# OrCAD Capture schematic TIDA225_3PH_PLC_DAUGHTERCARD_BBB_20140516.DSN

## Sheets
1 P05 - Zero Crossing Detector: size B; title: Zero Crossing Detector; rev: 1.2; company: Smart Grid Solutions; note: TIDA-00225_3PH_PLC_DAUGHTERCARD_BBB; note: Texas Instruments, Inc.; note: 12500 TI Blvd
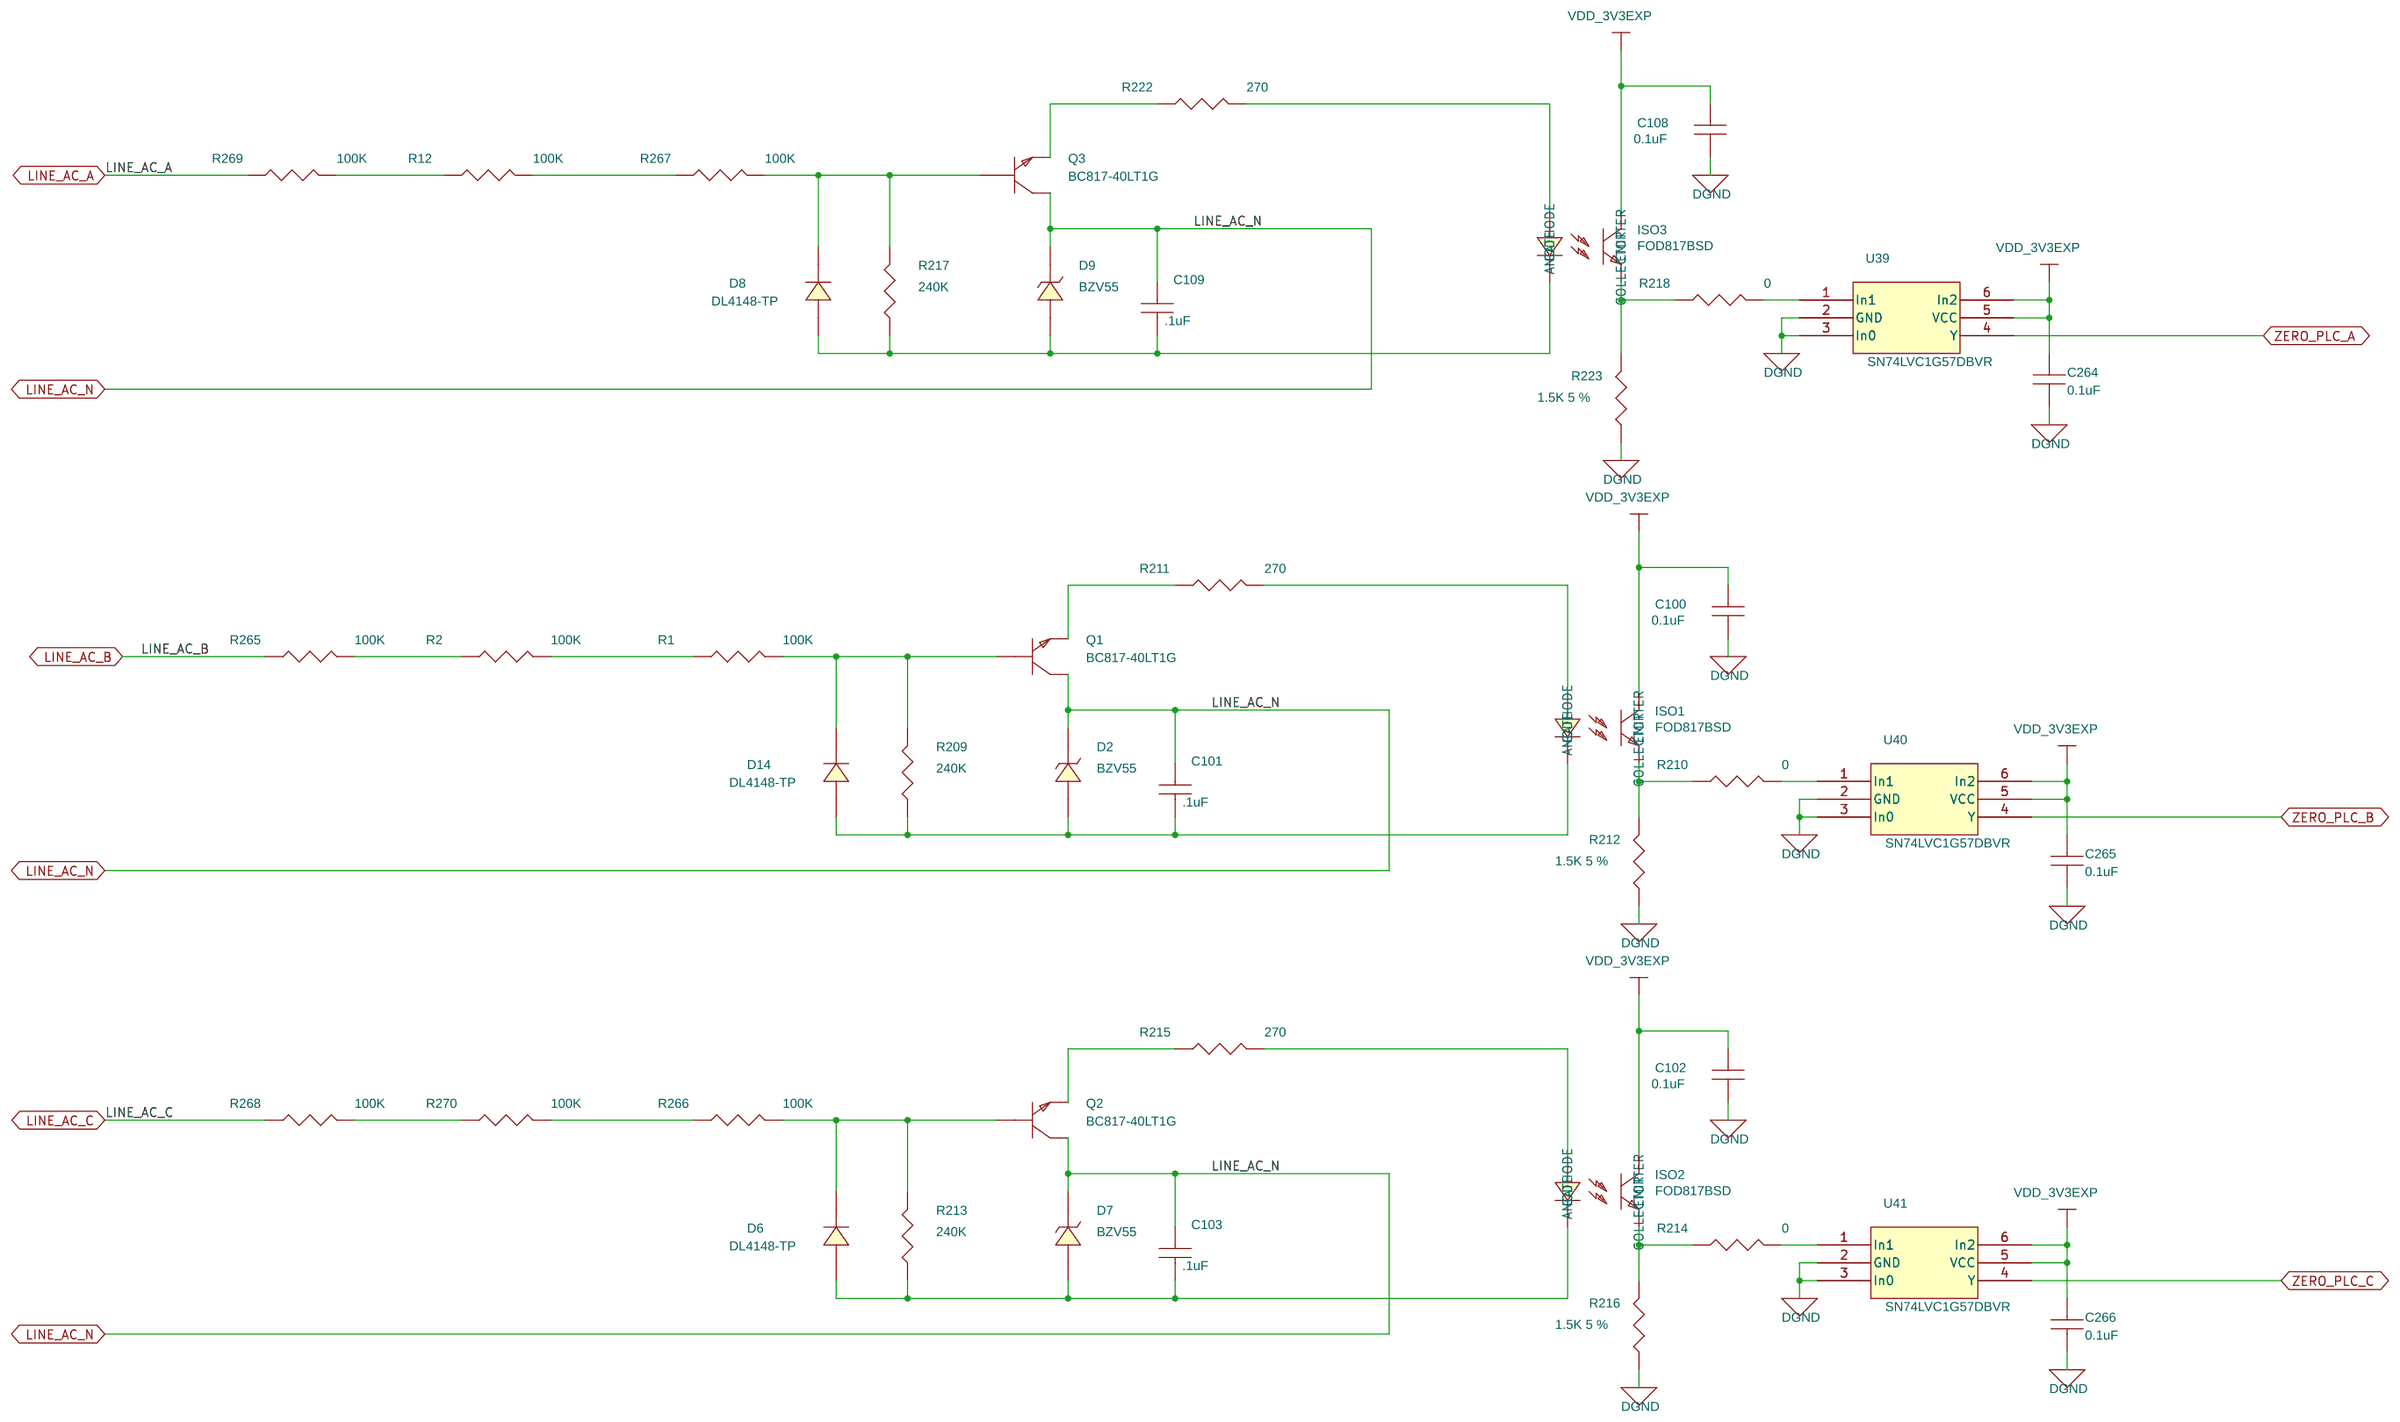
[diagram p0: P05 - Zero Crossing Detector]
2 P01 - Title Page: title: Title Page
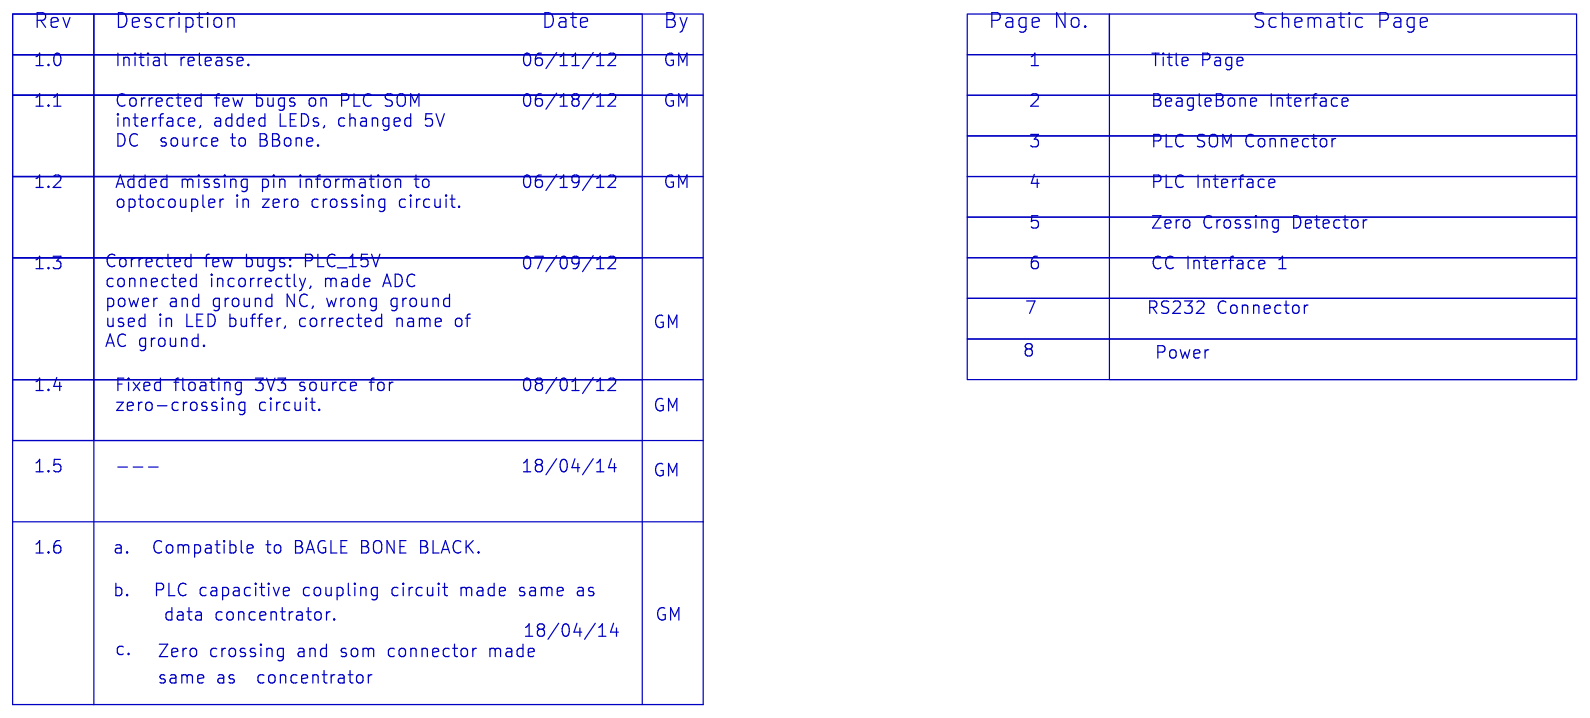
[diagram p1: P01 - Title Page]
3 P06 - CC Interface 1: size B; title: CC Interface 1
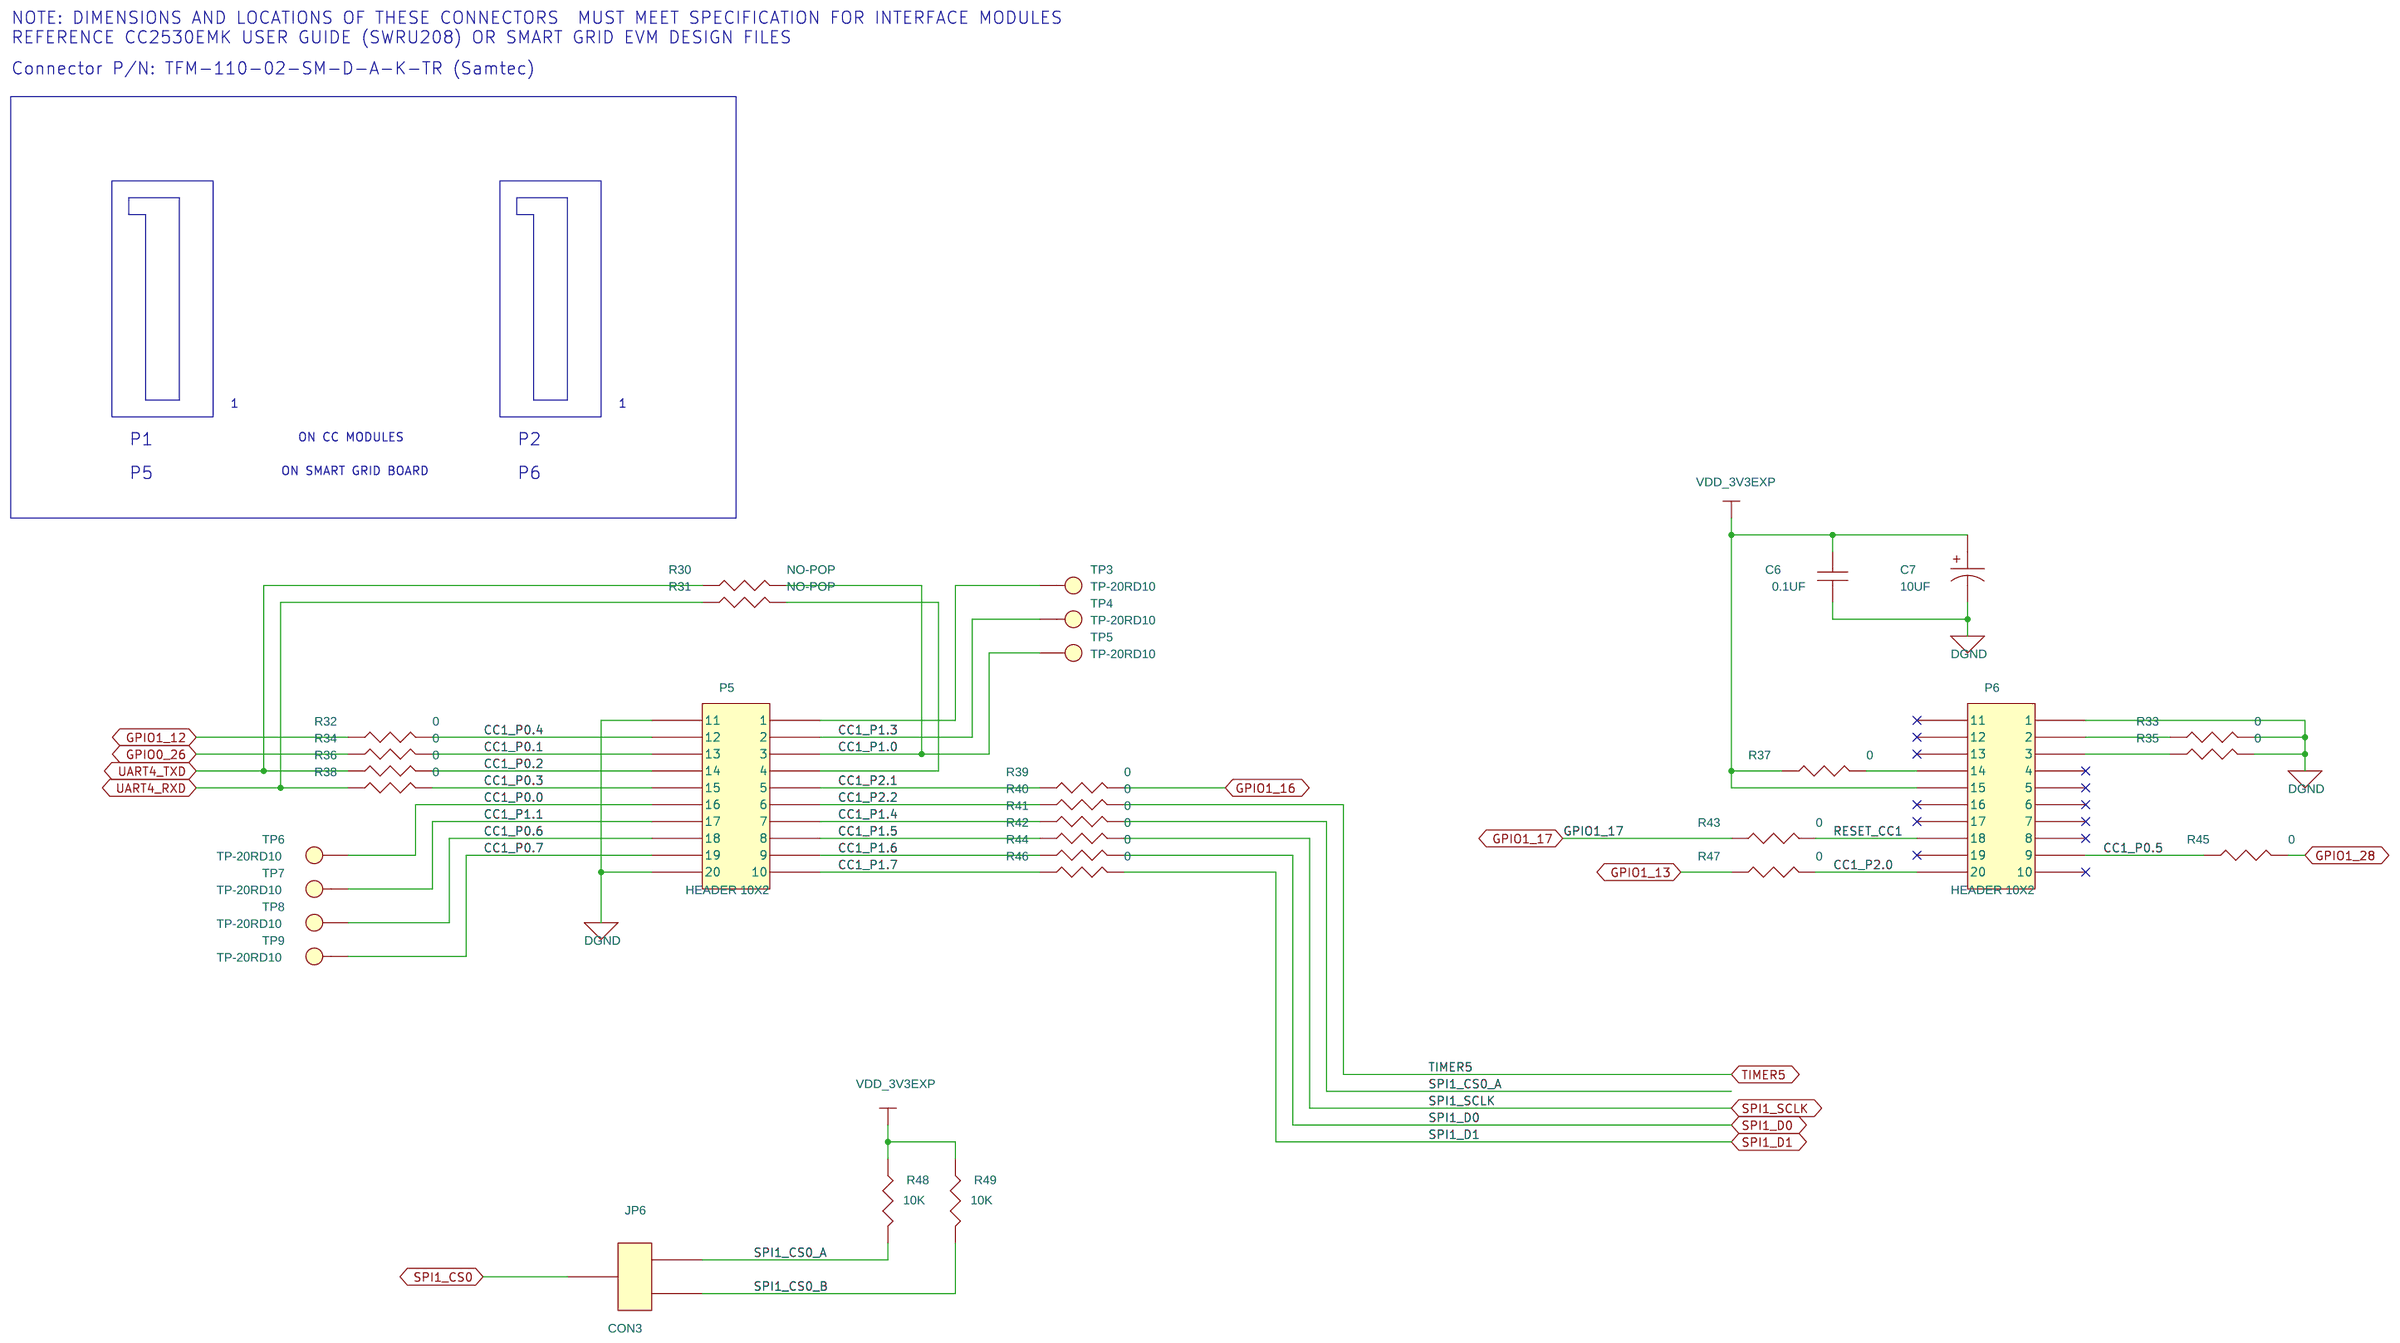
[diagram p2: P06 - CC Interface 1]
4 P04 - PLC Interface: size B; title: PLC Interface
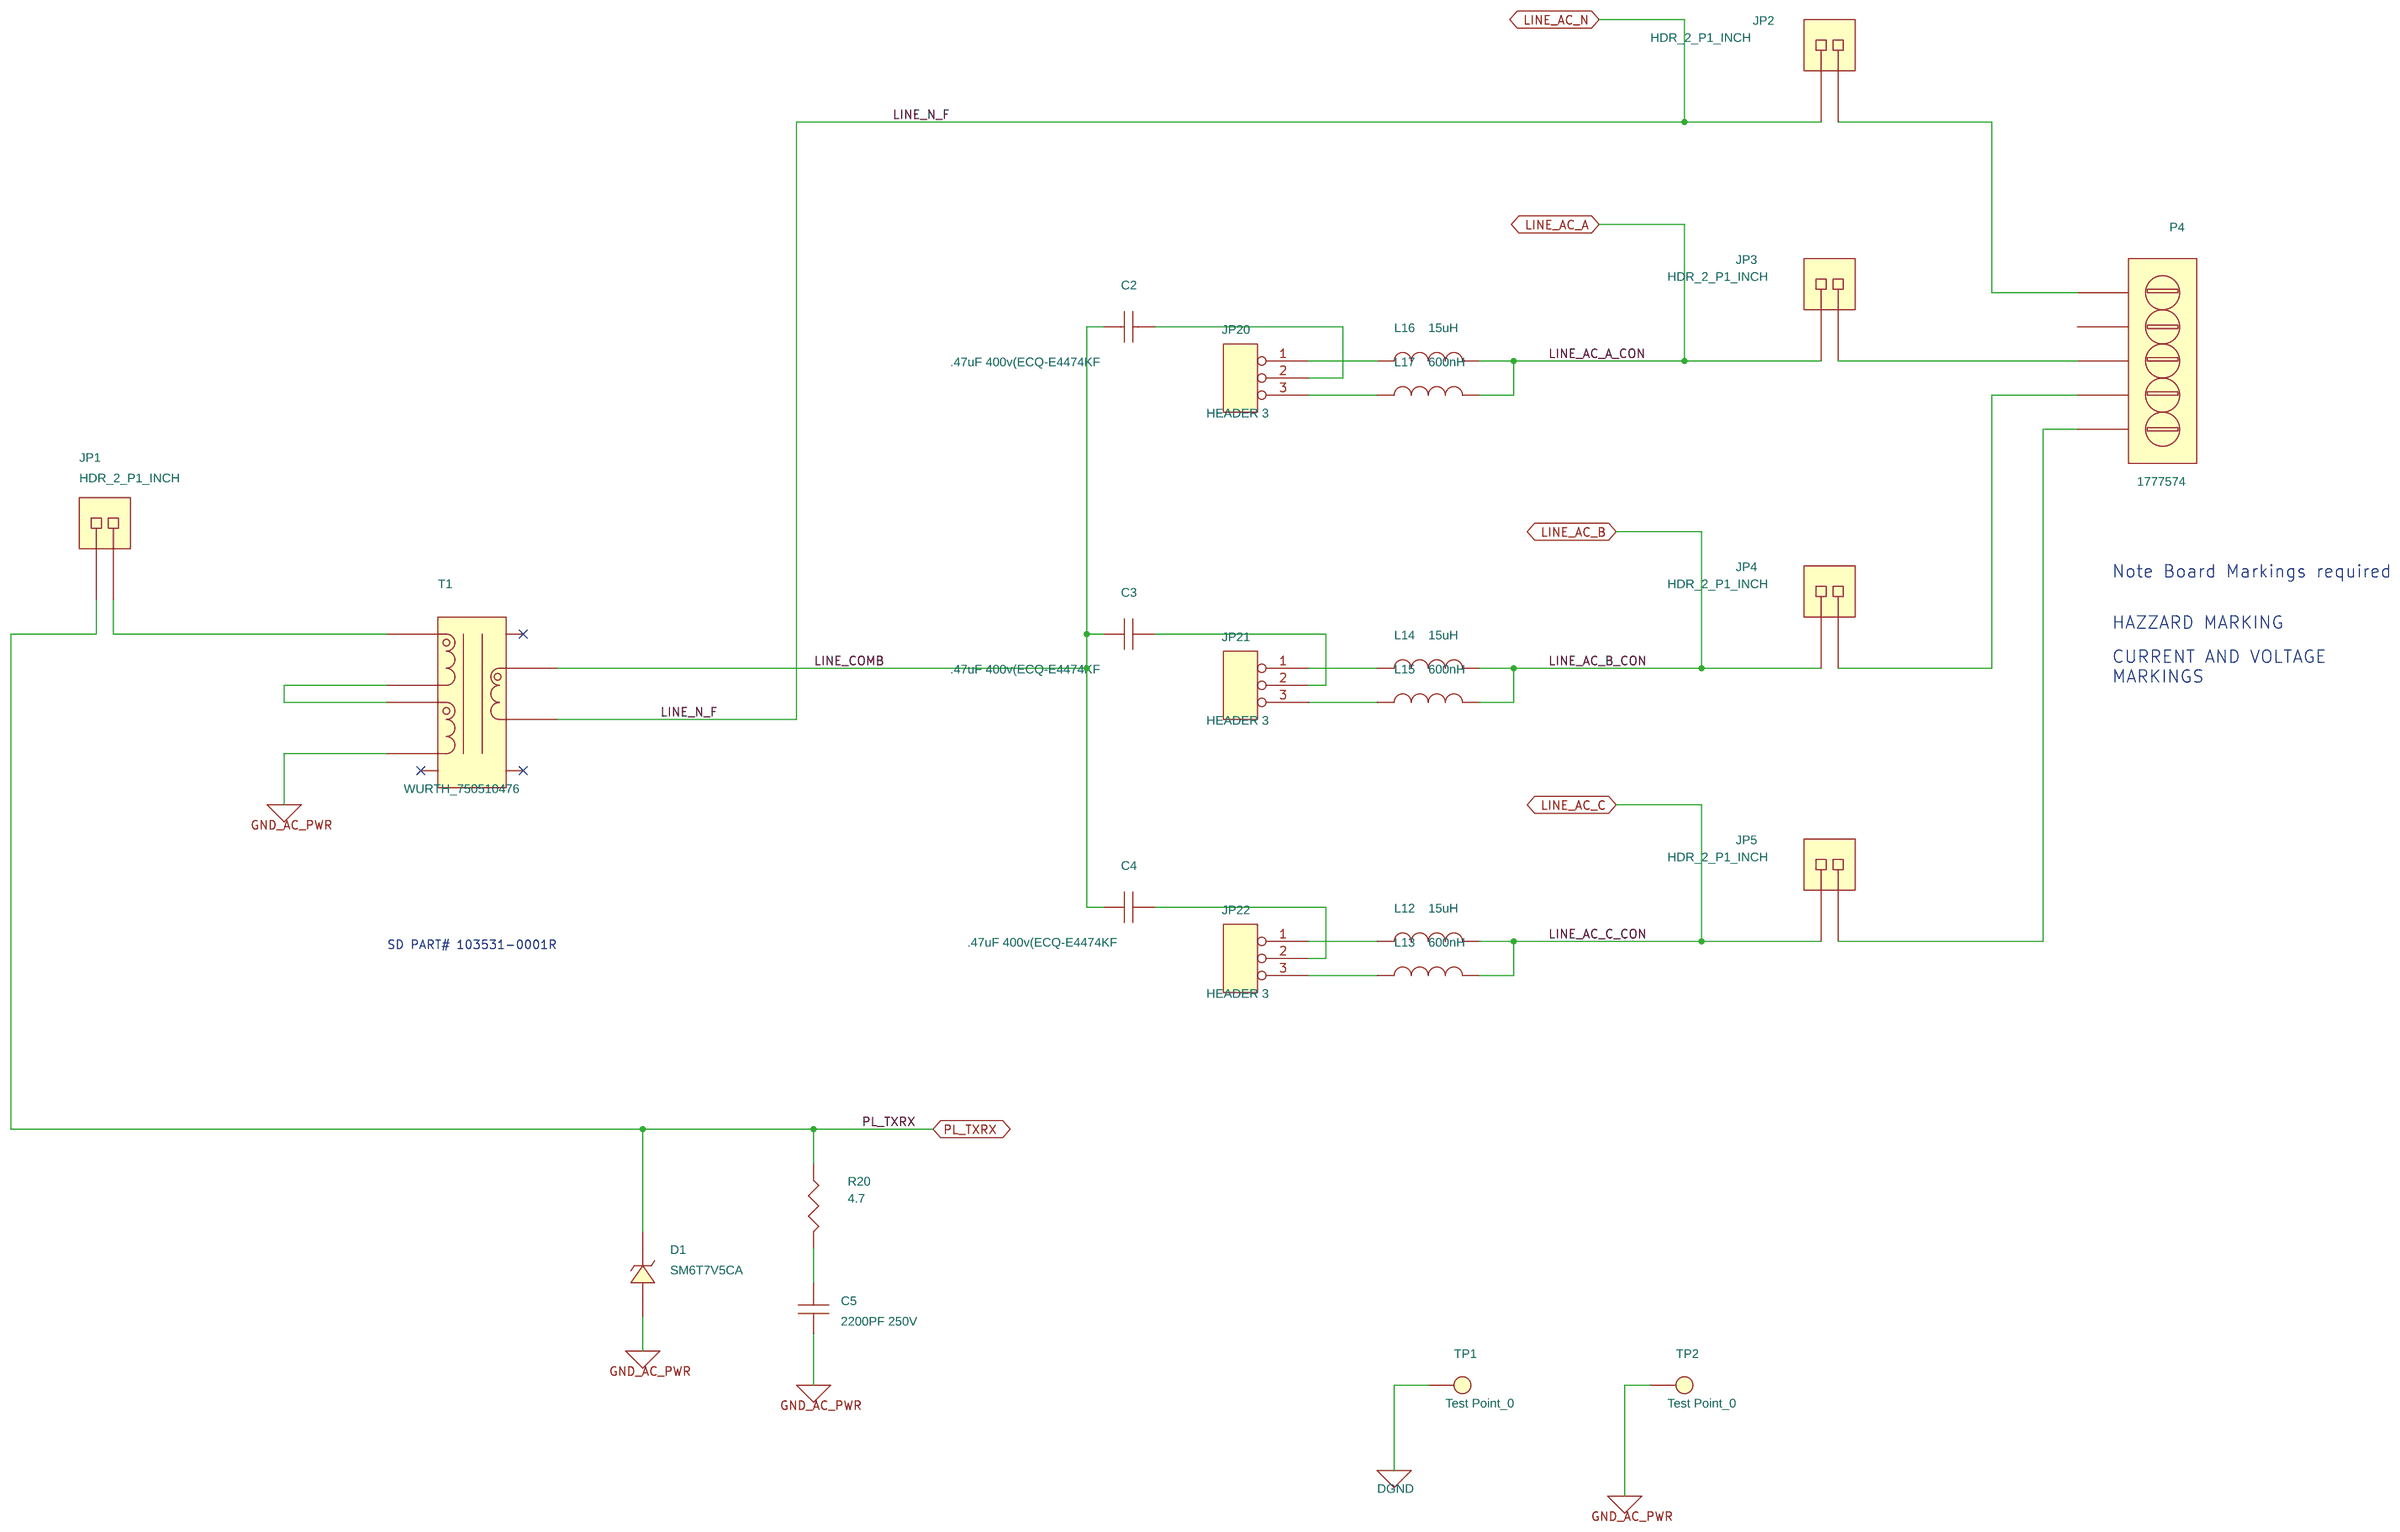
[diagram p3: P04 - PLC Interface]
5 P03 - PLC SOM Connector: size B; title: PLC SOM Connector
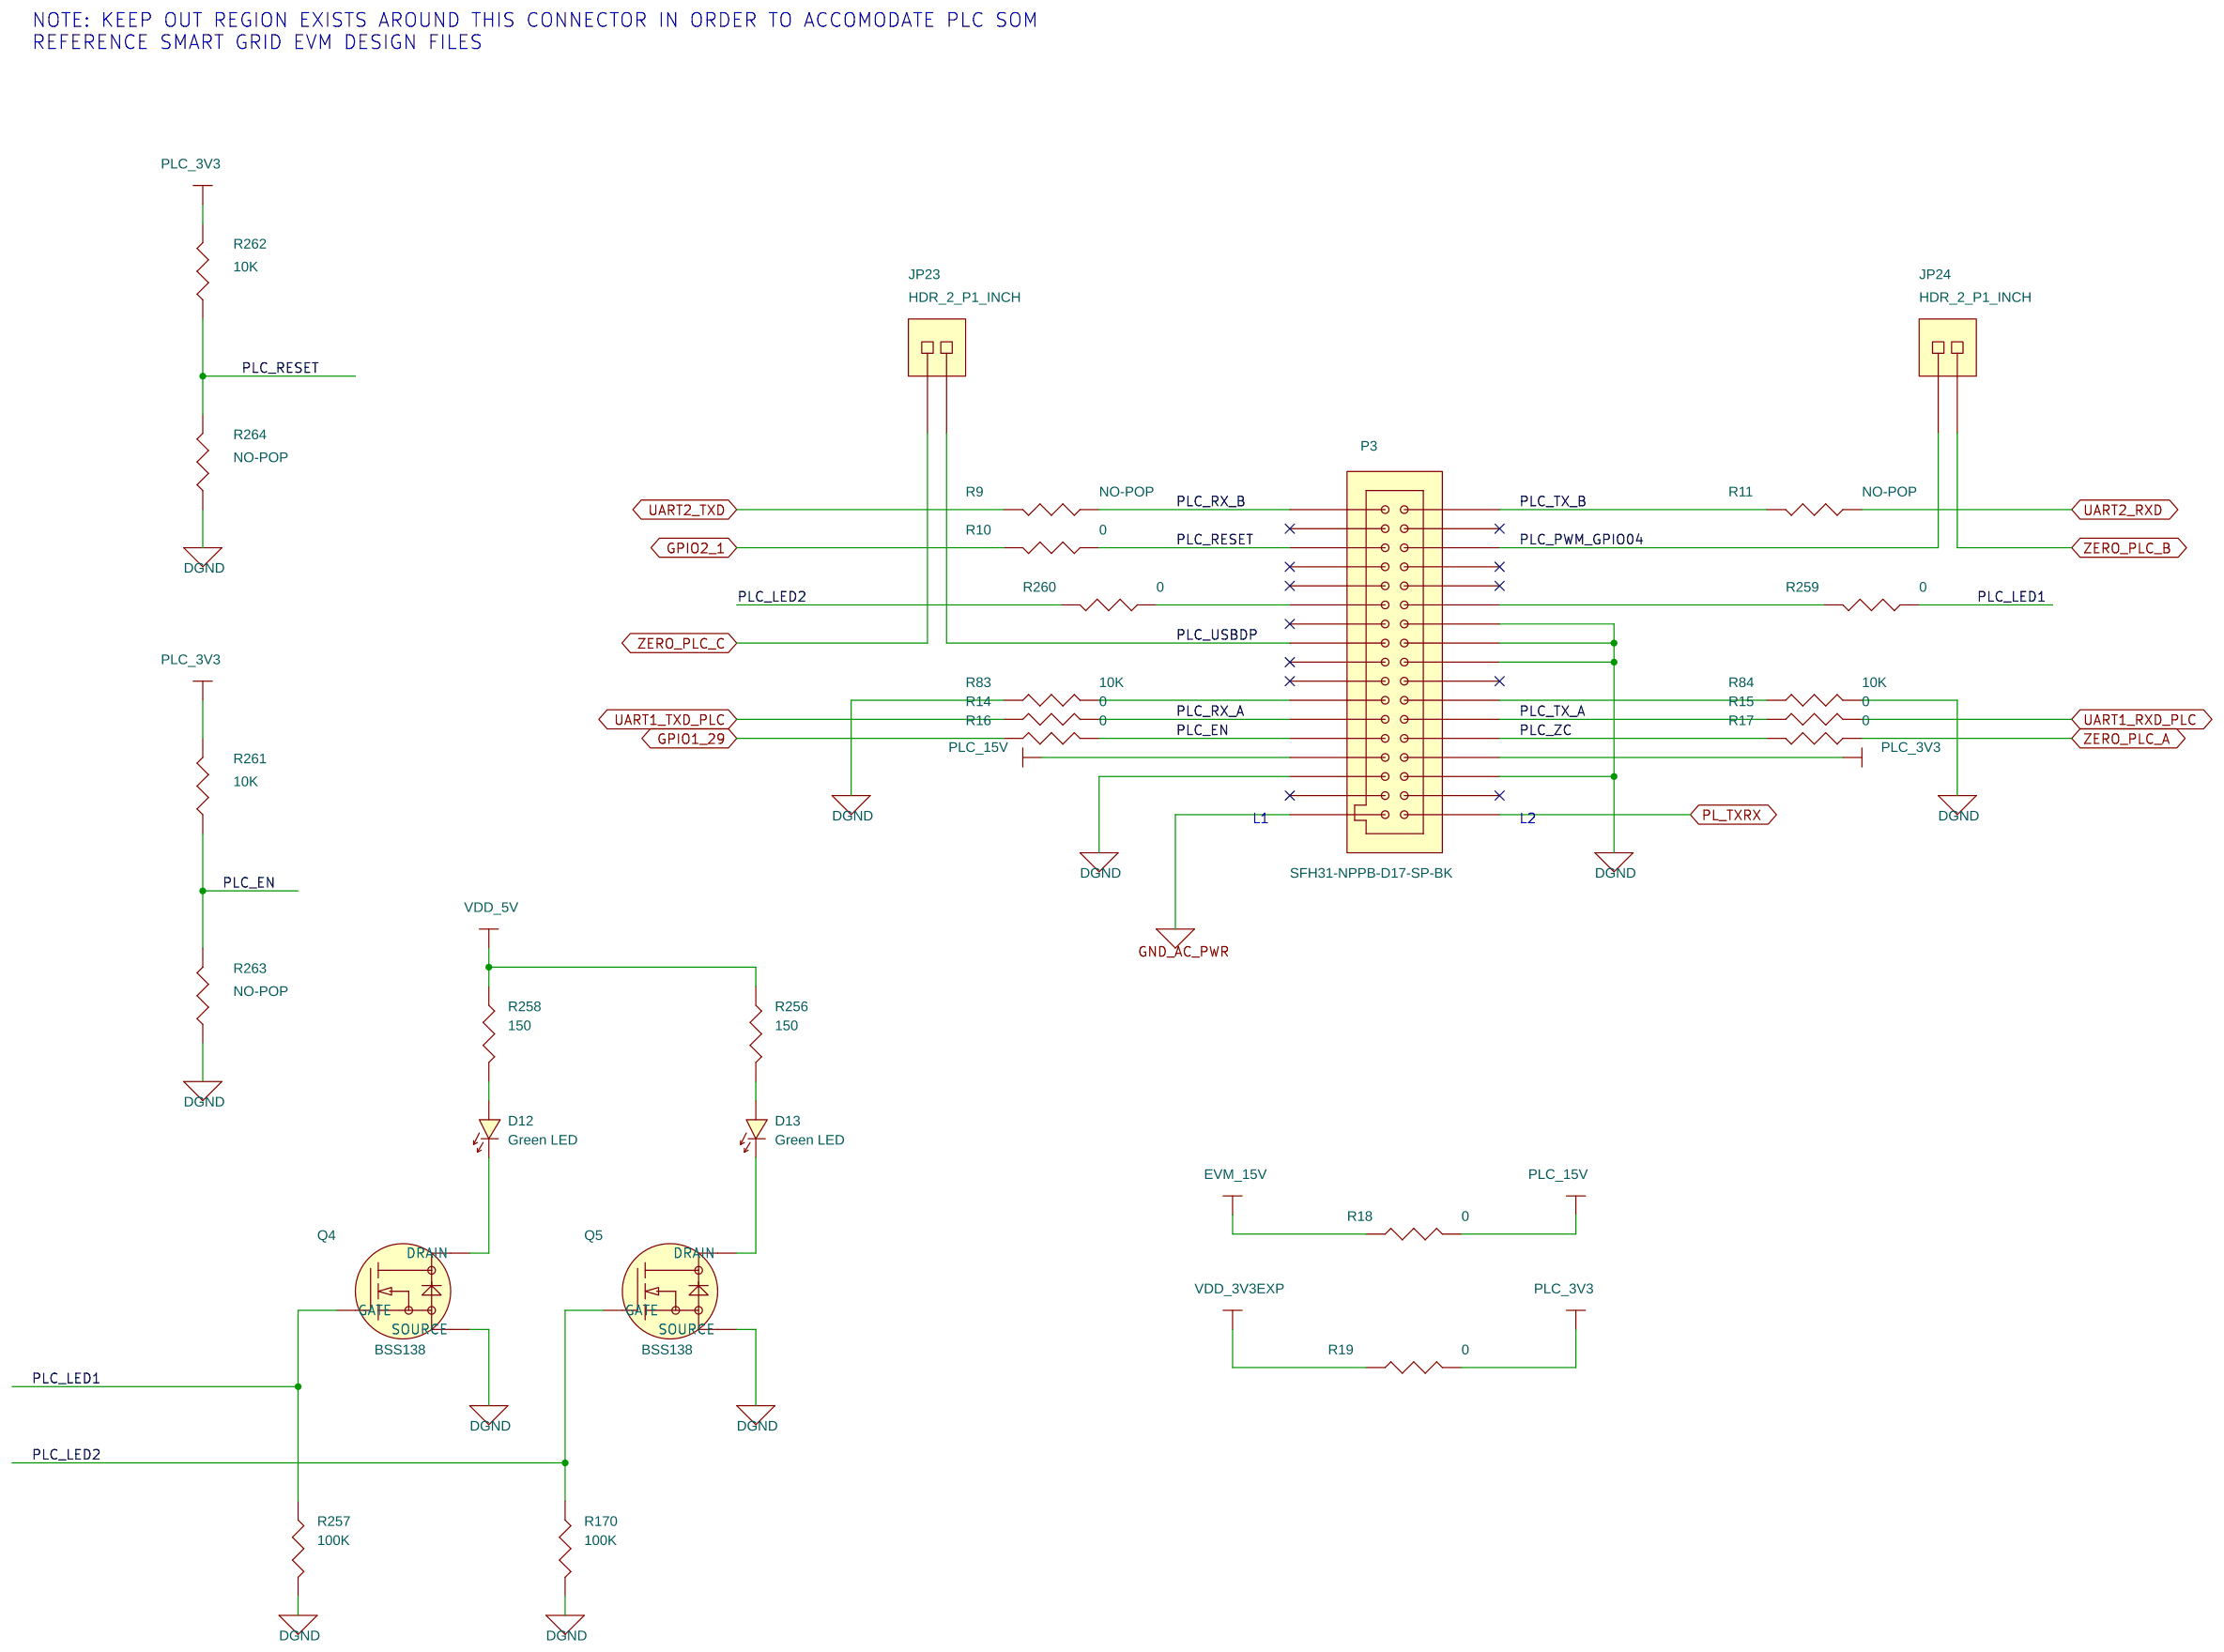
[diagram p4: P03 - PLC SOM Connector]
6 P07 - RS232 Connector: size B; title: RS232
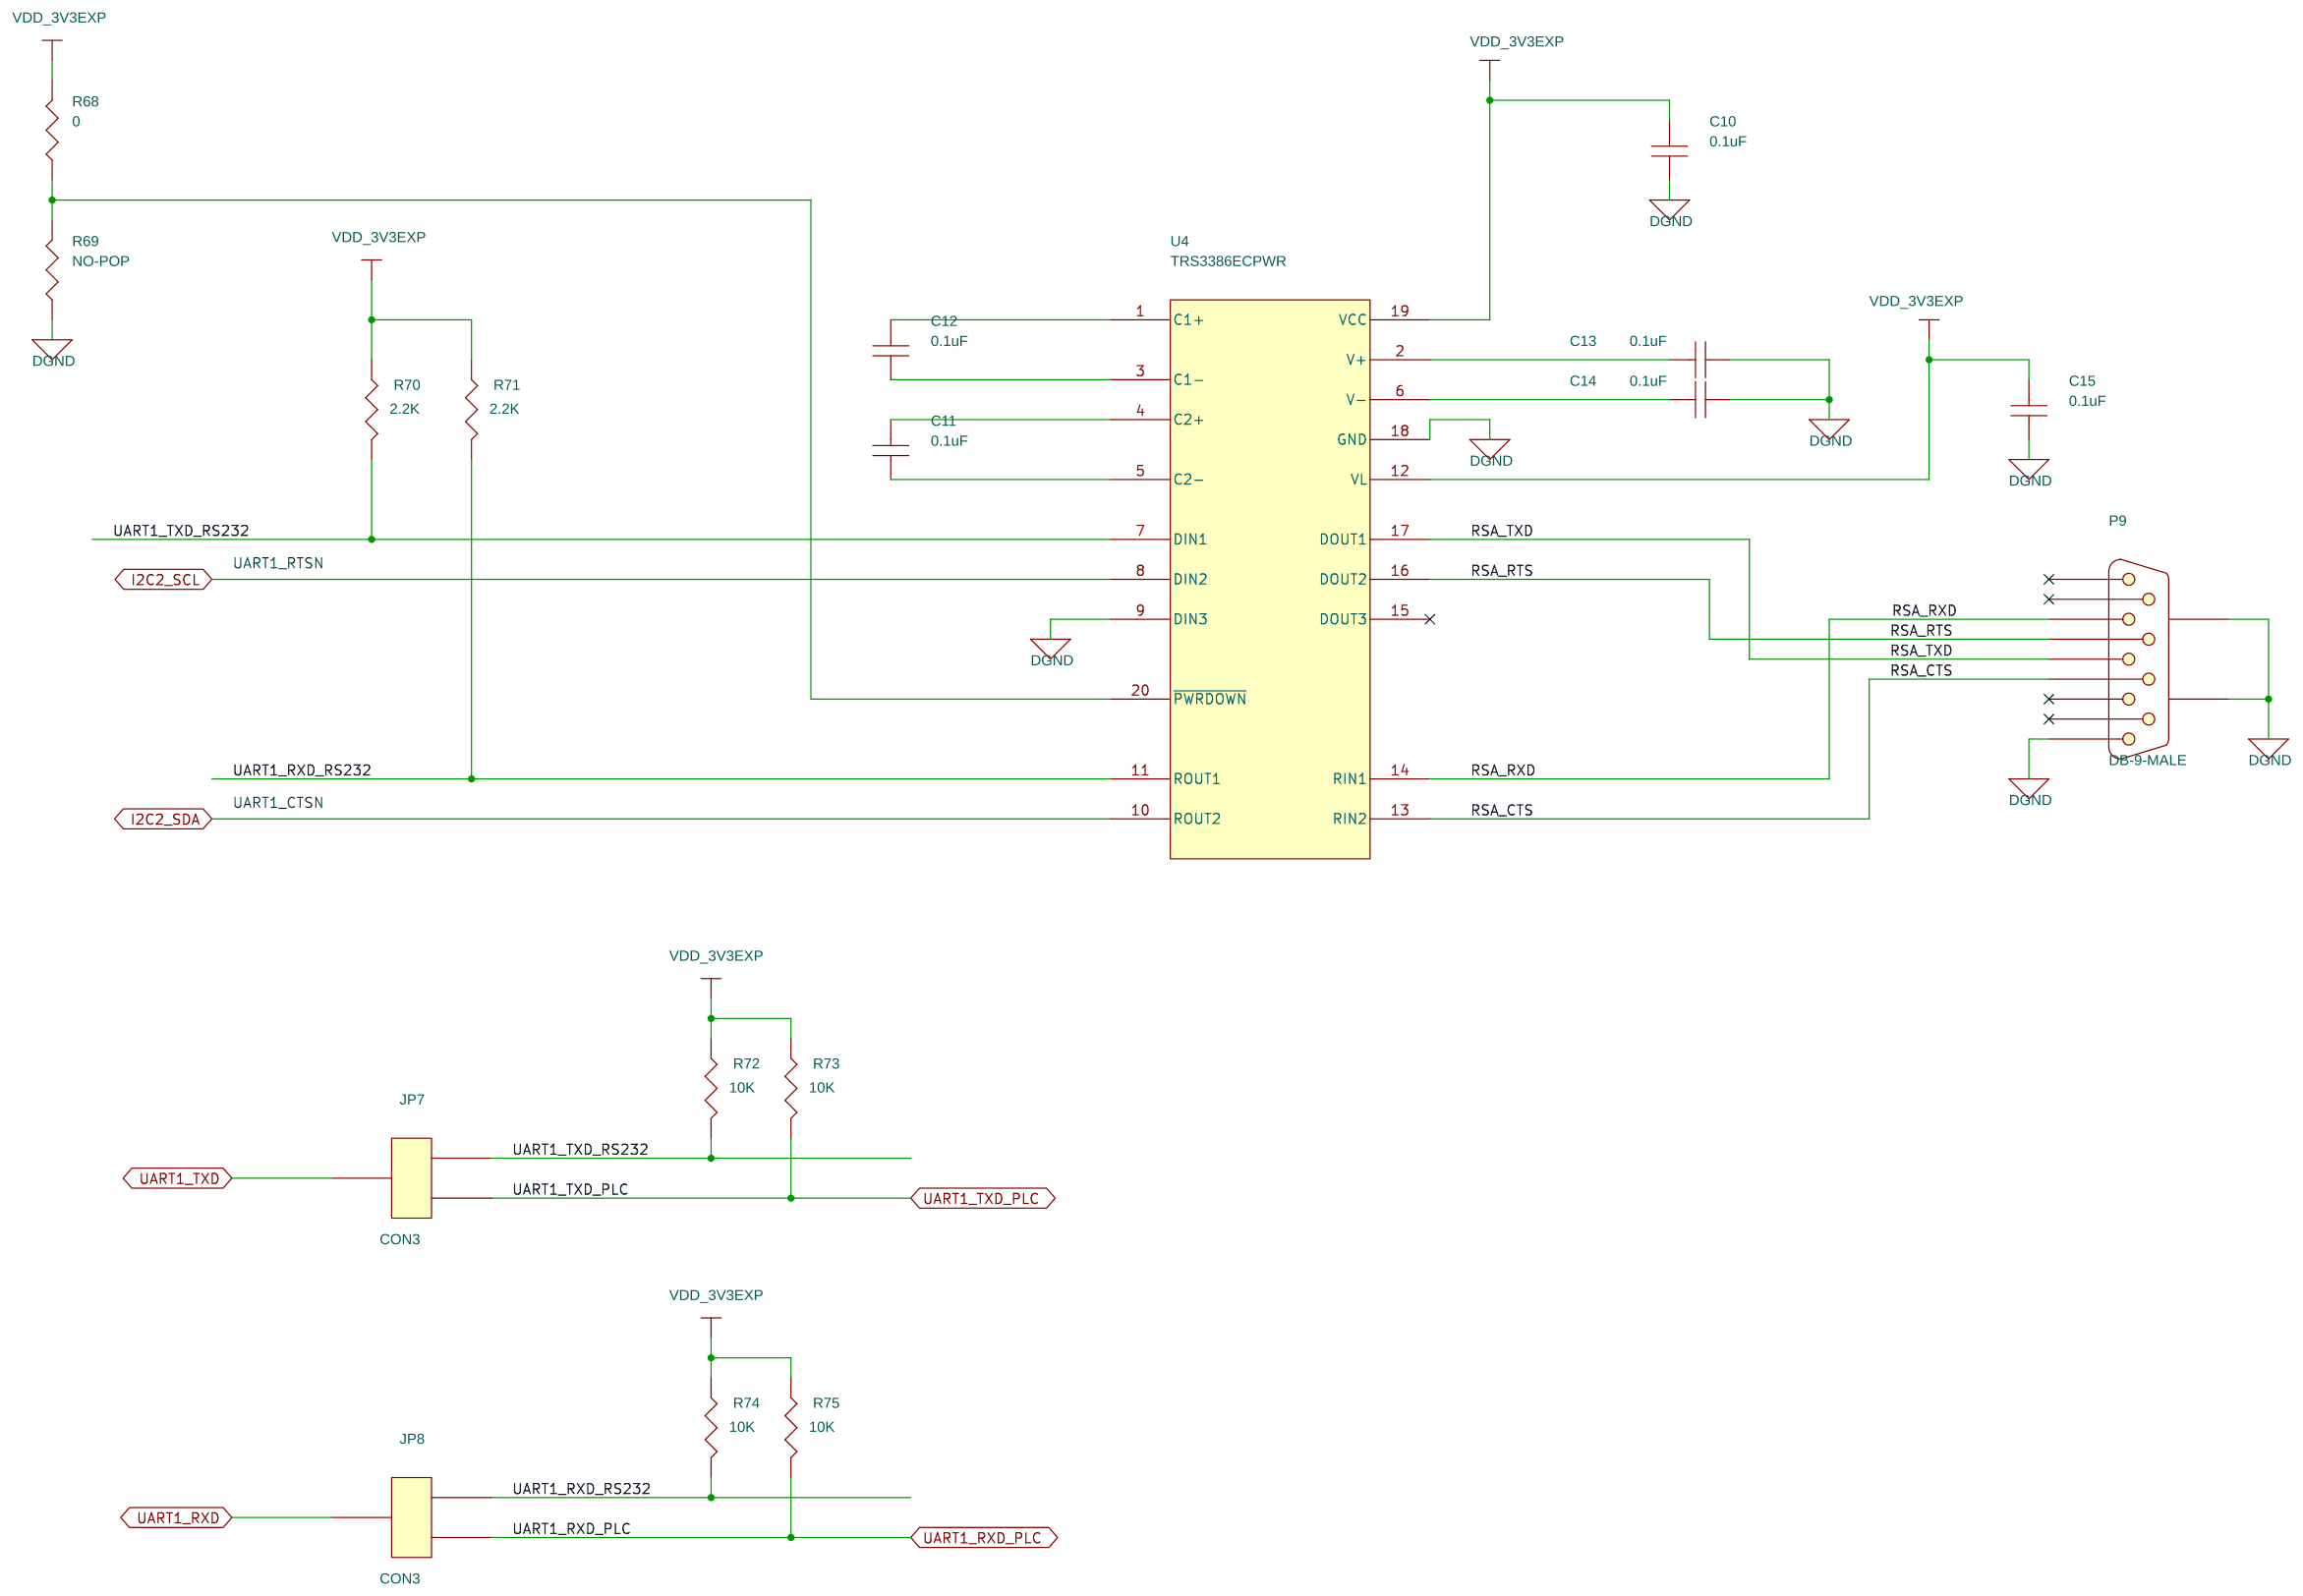
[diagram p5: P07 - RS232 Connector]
7 P08 - Power: size B; title: Power
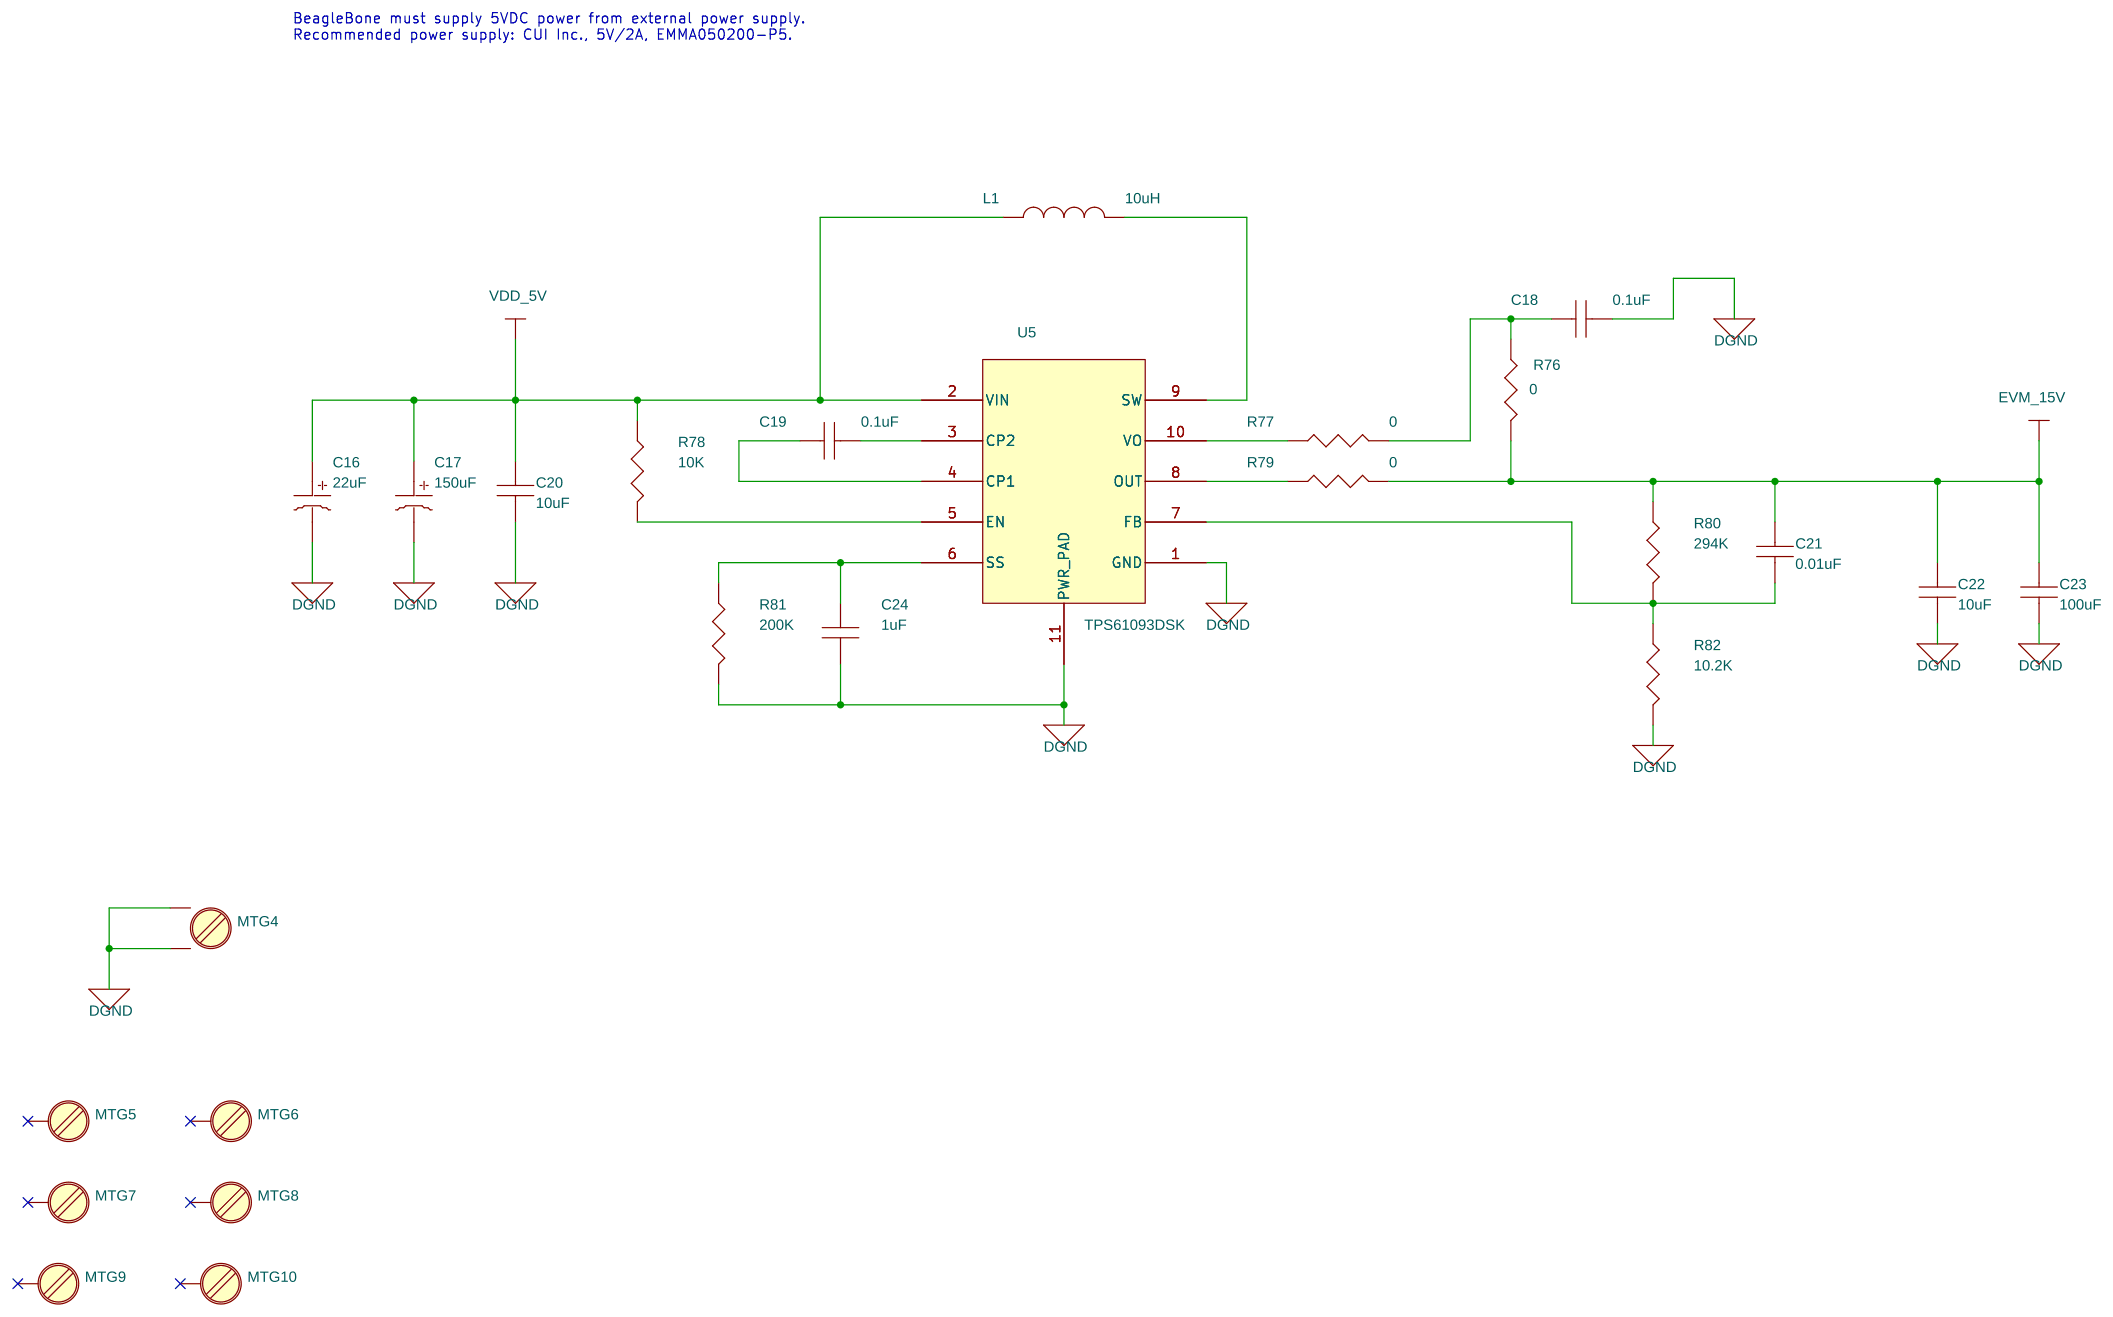
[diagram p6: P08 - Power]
8 P02 - BBone Interface: size B; title: BeagleBone Interface
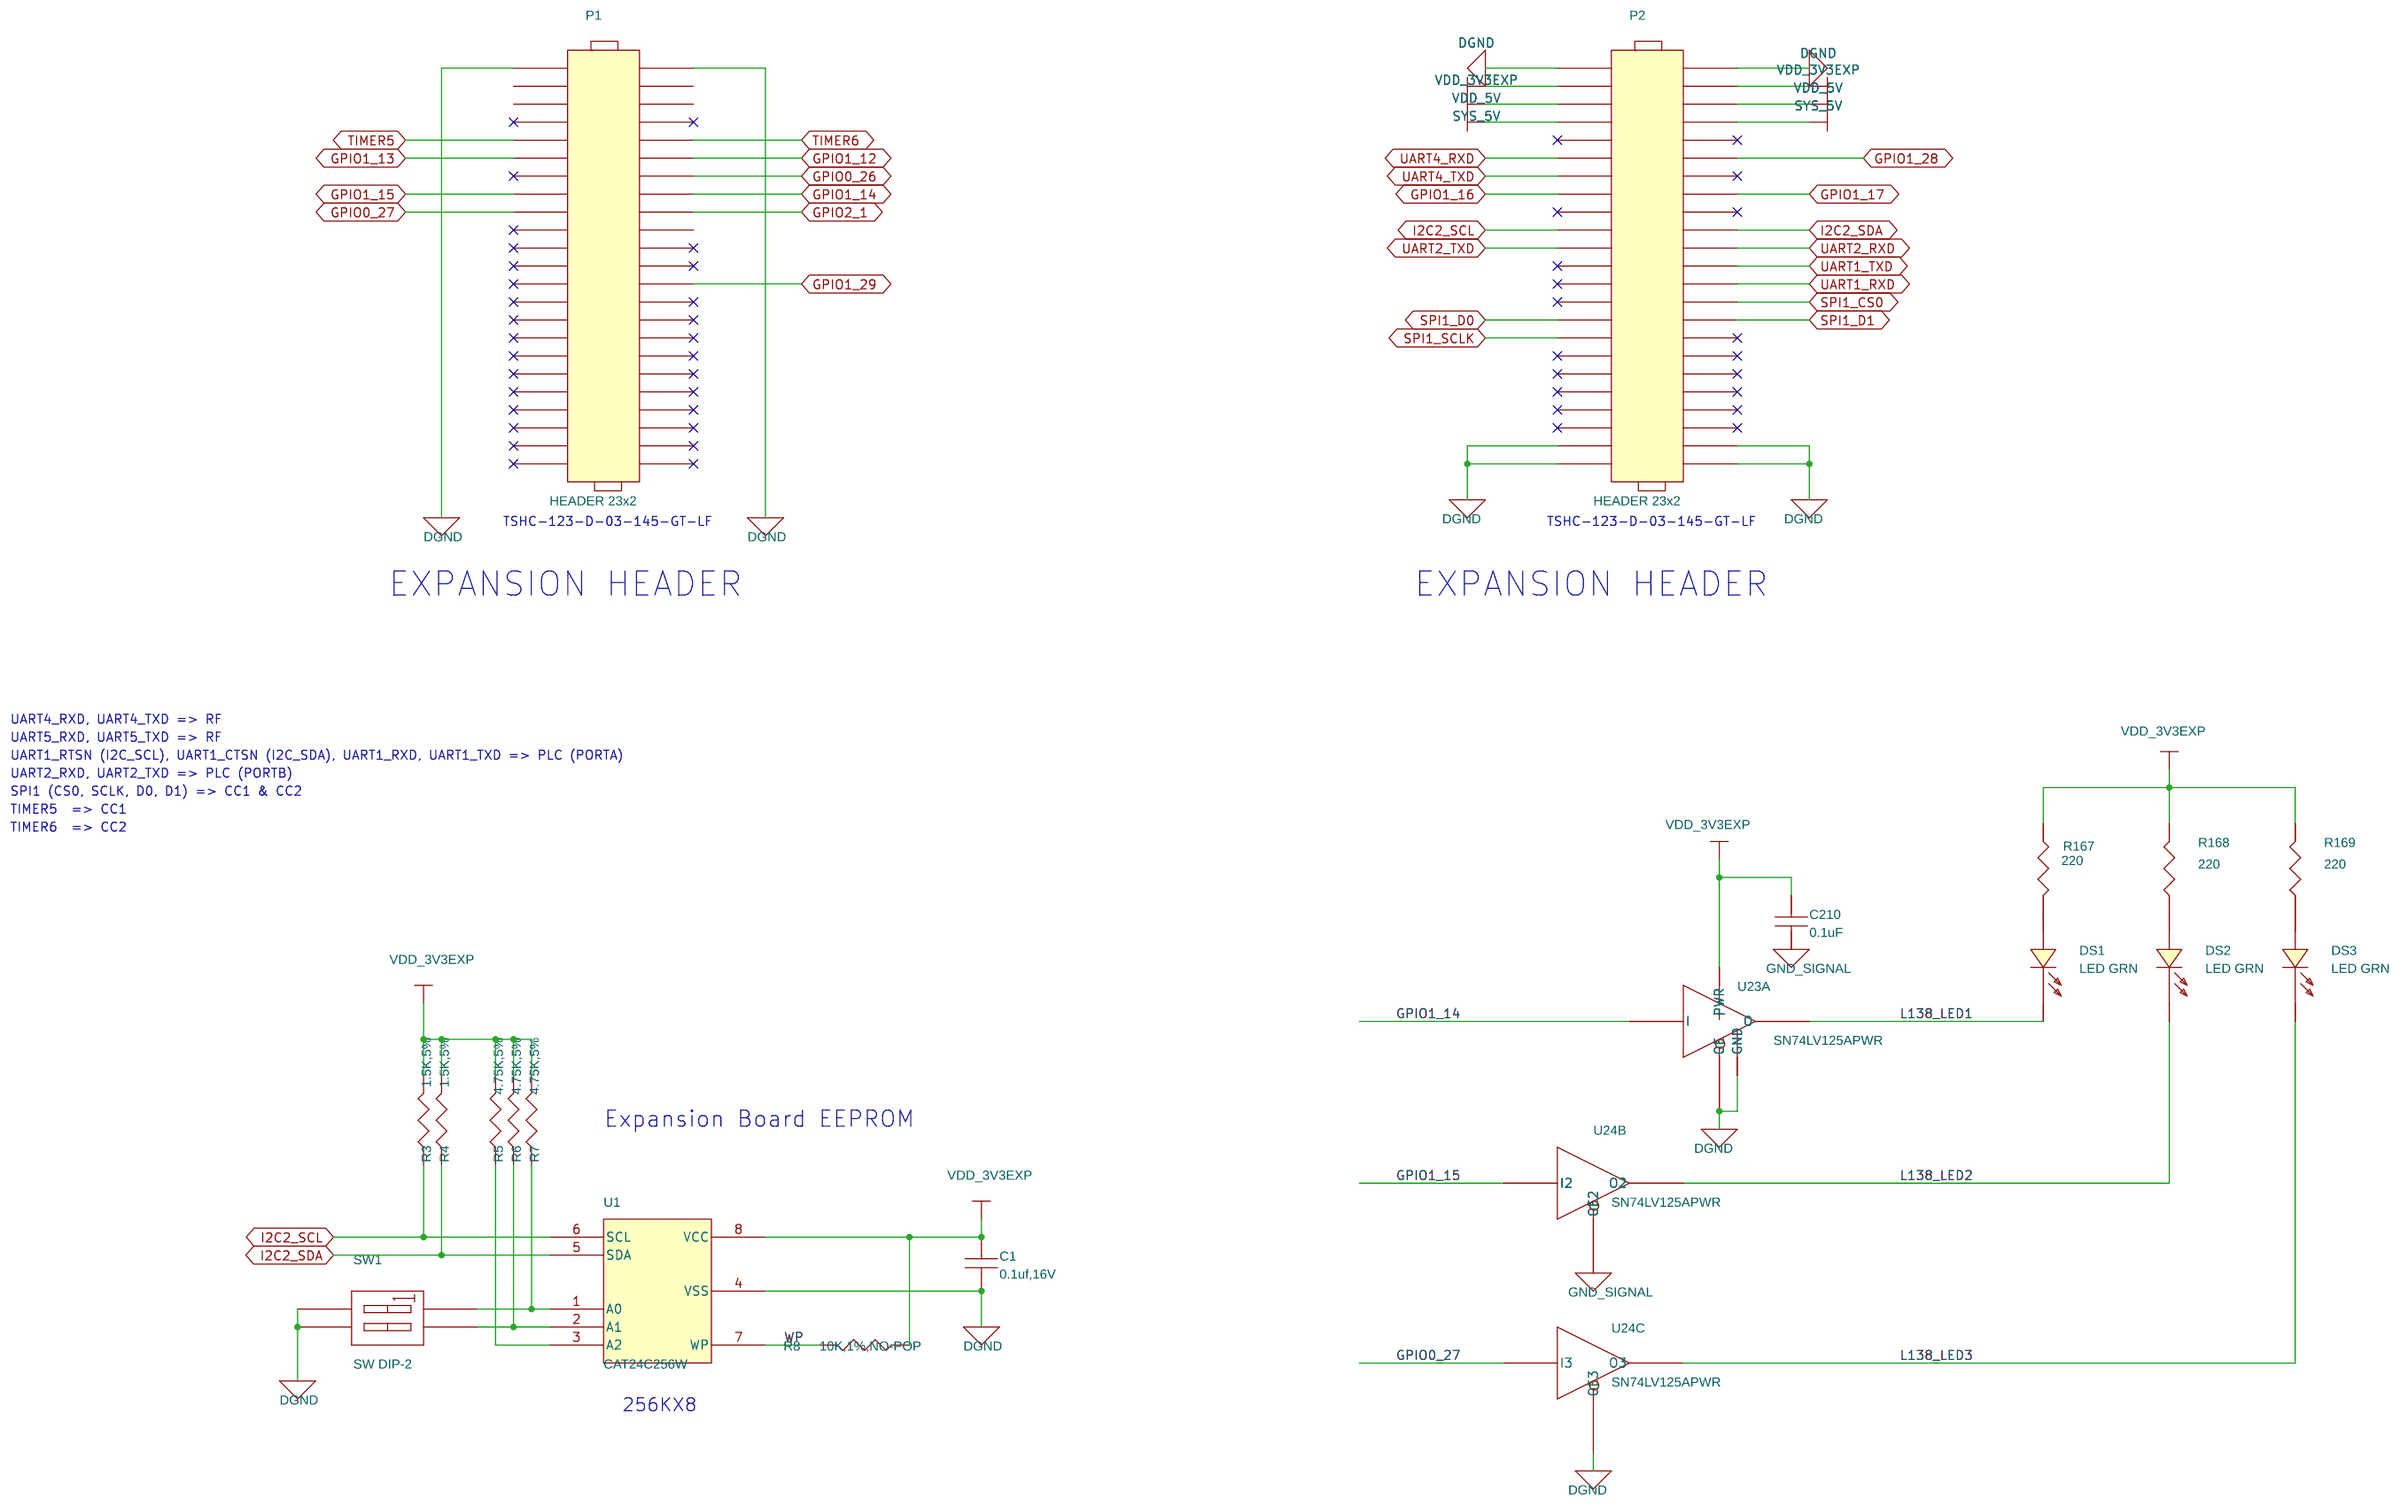
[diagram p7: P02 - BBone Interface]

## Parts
sheet P02 - BBone Interface
C1  0.1uf,16V  [0402]
C210  0.1uF  [0402]
DS1  LED GRN  [sm_led_0805_1]
DS2  LED GRN  [sm_led_0805_1]
DS3  LED GRN  [sm_led_0805_1]
P1  HEADER 23x2  [TSM-123-01-F-DV]
P2  HEADER 23x2  [TSM-123-01-F-DV]
R3  1.5K,5%  [0402]
R4  1.5K,5%  [0402]
R5  4.75K,5%  [0402]
R6  4.75K,5%  [0402]
R7  4.75K,5%  [0402]
R8  10K,1%,NO-POP  [0402]
R167  220  [0402]
R168  220  [0402]
R169  220  [0402]
SW1  SW DIP-2  [206-00011]
U1  CAT24C256W  [CAT24C256W]
U23  SN74LV125APWR  [SN74LV125APWR]  (section A)
U24  SN74LV125APWR  [SN74LV125APWR]  (sections B,C)
sheet P03 - PLC SOM Connector
D12  Green LED  [sm_led_0805_1]
D13  Green LED  [sm_led_0805_1]
JP23  HDR_2_P1_INCH  [M22-2510205]
JP24  HDR_2_P1_INCH  [M22-2510205]
P3  SFH31-NPPB-D17-SP-BK  [320-00014]
Q4  BSS138  [SOT23-3_1]
Q5  BSS138  [SOT23-3_1]
R9  NO-POP  [0402]
R10  0  [0402]
R11  NO-POP  [0402]
R14  0  [0402]
R15  0  [0402]
R16  0  [0402]
R17  0  [0402]
R18  0  [1206]
R19  0  [1206]
R83  10K  [1206]
R84  10K  [1206]
R170  100K  [0402]
R256  150  [0402]
R257  100K  [0402]
R258  150  [0402]
R259  0  [0402]
R260  0  [0402]
R261  10K  [1206]
R262  10K  [1206]
R263  NO-POP  [1206]
R264  NO-POP  [1206]
sheet P04 - PLC Interface
C2  .47uF 400v(ECQ-E4474KF  [C590-6545-728_1]
C3  .47uF 400v(ECQ-E4474KF  [C590-6545-728_1]
C4  .47uF 400v(ECQ-E4474KF  [C590-6545-728_1]
C5  2200PF 250V  [300-00048]
D1  SM6T7V5CA  [SM6T7V5CA]
JP1  HDR_2_P1_INCH  [M22-2510205]
JP2  HDR_2_P1_INCH  [M22-2510205]
JP3  HDR_2_P1_INCH  [M22-2510205]
JP4  HDR_2_P1_INCH  [M22-2510205]
JP5  HDR_2_P1_INCH  [M22-2510205]
JP20  HEADER 3  [M22-2510305]
JP21  HEADER 3  [M22-2510305]
JP22  HEADER 3  [M22-2510305]
L12  15uH  [ind-dr1040_1]
L13  600nH  [CHOKE2-P5-150X182_1]
L14  15uH  [ind-dr1040_1]
L15  600nH  [CHOKE2-P5-150X182_1]
L16  15uH  [ind-dr1040_1]
L17  600nH  [CHOKE2-P5-150X182_1]
P4  1777574  [1777574]
R20  4.7  [0805]
T1  WURTH_750510476  [750510476]
TP1  Test Point_0  [TP-60RD40]
TP2  Test Point_0  [TP-60RD40]
sheet P05 - Zero Crossing Detector
C100  0.1uF  [0805]
C101  .1uF  [0603]
C102  0.1uF  [0805]
C103  .1uF  [0603]
C108  0.1uF  [0805]
C109  .1uF  [0603]
C264  0.1uF  [0402]
C265  0.1uF  [0402]
C266  0.1uF  [0402]
D2  BZV55  [SOD80-50X80_1]
D6  DL4148-TP  [minimelf_1]
D7  BZV55  [SOD80-50X80_1]
D8  DL4148-TP  [minimelf_1]
D9  BZV55  [SOD80-50X80_1]
D14  DL4148-TP  [minimelf_1]
ISO1  FOD817BSD  [dip4-60x55_1]
ISO2  FOD817BSD  [dip4-60x55_1]
ISO3  FOD817BSD  [dip4-60x55_1]
Q1  BC817-40LT1G  [sot23-28x44_1]
Q2  BC817-40LT1G  [sot23-28x44_1]
Q3  BC817-40LT1G  [sot23-28x44_1]
R1  100K  [0603]
R2  100K  [0603]
R12  100K  [0603]
R209  240K  [0603]
R210  0  [0603]
R211  270  [0603]
R212  1.5K 5 %  [0805]
R213  240K  [0603]
R214  0  [0603]
R215  270  [0603]
R216  1.5K 5 %  [0805]
R217  240K  [0603]
R218  0  [0603]
R222  270  [0603]
R223  1.5K 5 %  [0805]
R265  100K  [0603]
R266  100K  [0603]
R267  100K  [0603]
R268  100K  [0603]
R269  100K  [0603]
R270  100K  [0603]
U39  SN74LVC1G57DBVR  [DBV6-27X39-6]
U40  SN74LVC1G57DBVR  [DBV6-27X39-6]
U41  SN74LVC1G57DBVR  [DBV6-27X39-6]
sheet P06 - CC Interface 1
C6  0.1UF  [0402]
C7  10UF  [1206]
JP6  CON3  [M22-2510305]
P5  HEADER 10X2  [320-00027]
P6  HEADER 10X2  [320-00027]
R30  NO-POP  [0402]
R31  NO-POP  [0402]
R32  0  [0402]
R33  0  [0402]
R34  0  [0402]
R35  0  [0402]
R36  0  [0402]
R37  0  [0402]
R38  0  [0402]
R39  0  [0402]
R40  0  [0402]
R41  0  [0402]
R42  0  [0402]
R43  0  [0402]
R44  0  [0402]
R45  0  [0402]
R46  0  [0402]
R47  0  [0402]
R48  10K  [0402]
R49  10K  [0402]
TP3  TP-20RD10  [tp-20RD10]
TP4  TP-20RD10  [tp-20RD10]
TP5  TP-20RD10  [tp-20RD10]
TP6  TP-20RD10  [tp-20RD10]
TP7  TP-20RD10  [tp-20RD10]
TP8  TP-20RD10  [tp-20RD10]
TP9  TP-20RD10  [tp-20RD10]
sheet P07 - RS232 Connector
C10  0.1uF  [0402]
C11  0.1uF  [0402]
C12  0.1uF  [0402]
C13  0.1uF  [0402]
C14  0.1uF  [0402]
C15  0.1uF  [0402]
JP7  CON3  [M22-2510305]
JP8  CON3  [M22-2510305]
P9  DB-9-MALE  [1734351-1]
R68  0  [0402]
R69  NO-POP  [0402]
R70  2.2K  [0402]
R71  2.2K  [0402]
R72  10K  [0402]
R73  10K  [0402]
R74  10K  [0402]
R75  10K  [0402]
U4  TRS3386ECPWR  [TRS3386ECPWR]
sheet P08 - Power
C16  22uF  [3528]
C17  150uF  [6032]
C18  0.1uF  [0603]
C19  0.1uF  [0402]
C20  10uF  [1206]
C21  0.01uF  [0402]
C22  10uF  [3528]
C23  100uF  [7343]
C24  1uF  [0603]
L1  10uH  [CDRH5D18NP-100NC]
MTG4  MOUNTING SCREW  [490-00002]
MTG5  MOUNTING SCREW  [MH-3.2]
MTG6  MOUNTING SCREW  [MH-3.2]
MTG7  MOUNTING SCREW  [MH-3.2]
MTG8  MOUNTING SCREW  [MH-3.2]
MTG9  MOUNTING SCREW  [MH-3.2]
MTG10  MOUNTING SCREW  [MH-3.2]
R76  0  [0603]
R77  0  [0603]
R78  10K  [0402]
R79  0  [0603]
R80  294K  [0402]
R81  200K  [0402]
R82  10.2K  [0402]
U5  TPS61093DSK  [TPS61093DSK]

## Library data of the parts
C1 = CAP_0.1uF_X7R_16V_10%_0402
C6 C19 C210 = CAP: PART_N: 101587-1100R; Part #: 101587-1100R
DS1-DS3 = LED_2: PART_N: 100823-0001R; Part #: 100823-0001R; SD PCB Footprint: EIA1206D
P1 P2 = HEADER_23x2
R3-R8 = RES_0_1_16W_1%_0402
R167 = R: Resistor, 5%, 1/10W; PART_N: 101370-2201R; Part #: 101370-2201R; SD PCB Footprint: EIA0603
R168 R169 = R_0: PART_N: 101370-3601R; Part #: 101370-3601R
SW1 = SW_DIP-2
U1 = CAT24C256W
U23 U24 = SN74LVC125PW: PART_N: 102288-0001R; Part #: 102288-0001R
D12 D13 = LED_Green
JP1-JP5 JP23 JP24 = HDR_2_P1_INCH: PART_N: 100115-0002R; Part #: 100115-0002R
P3 = SFH31-NPPB-D17-SP-BK: PART_N: 103535-0017R; Part #: 103535-0017R
Q4 Q5 = MOSFET_NChan_BSS138
R9-R11 R30 R31 R259 R260 = R: PART_N: R0402-NOPOP; Part #: R0402-NOPOP
R14-R17 R32-R47 = R: PART_N: 101370-0001R; Part #: 101370-0001R
R18 R19 R83 R84 R261-R264 = R: PART_N: 100155-0001R; Part #: 100155-0001R
R170 R257 = 100KOhmResistor1_16W0402
R256 R258 = 150ohm1_16W1%SMD0402
C2-C4 = ECQE2475: PART_N: 101410-1470R; Part #: 101410-1470R
C5 = CAP: PART_N: 103532-1222R; Part #: 103532-1222R
D1 = DIODE_ZENER_0: PART_N: 104356-0001R; Part #: 104356-0001R
JP20-JP22 = HEADER3Pin: PART_N: 100115-0003R; Part #: 100115-0003R
L12 L14 L16 = 2.2uHInductor10%2.6Asmd: PART_N: 103084-0150R; Part #: 103084-0150R
L13 L15 L17 = 2.2uHInductor10%2.6Asmd: PART_N: 104357-0600R; Part #: 104357-0600R
P4 = 1777574
R20 = R: PART_N: 100552-0470R; Part #: 100552-0470R
T1 = WURTH_2
TP1 TP2 = Test_Point_0: PART_N: TP-NO-POP; Part #: TP-NO-POP
C100 C102 C108 = 0.1uF: PART_N: 100201-1100R
C101 C103 C109 = CAP_.1_uF_10%_0603_50V: PART_N: x; Part #: x
C264-C266 = 0.1uFCapacitor16V10%0402
D2 D7 D9 = DIODE_ZENER_0: PART_N: 103530-0001R; Part #: 103530-0001R
D6 D8 D14 = DL4148-TP_0: PART_N: 100391-0001R
ISO1-ISO3 = FOD817BSD: PART_N: 103528-0001R; Part #: 103528-0001R
Q1-Q3 = TRANS-NPN-BC817-40LT1G: PART_N: 103529-0001R; Part #: 103529-0001R
R1 R2 R12 R265-R270 = RES_270_5%_0603: PART_N: 100687-1004R; Part #: 100687-1004R
R209 R213 R217 = RES_270_5%_0603: PART_N: 100687-2404R; Part #: 100687-2404R
R210 R214 R218 = RES_270_5%_0603: PART_N: 100687-0001R; Part #: 100687-0001R
R211 R215 R222 = RES_270_5%_0603: PART_N: 100687-2701R
R212 R216 R223 = 1.5K_5_%: PART_N: 100552-1502R
U39-U41 = SN74LVC1G57DBVR
C7 = CAP_POL: PART_N: 101003-0101R; Part #: 101003-0101R
JP6-JP8 = CON3_0: PART_N: 100115-0003R; Part #: 100115-0003R
P5 P6 = HEADER_10X2_0_v2: PART_N: 103285-0010R; Part #: 103285-0010R
R48 R49 R72-R75 R78 = R: PART_N: 101370-1003R; Part #: 101370-1003R
TP3-TP9 = Test_Point_0: PART_N: TP-20RD10-NO-POP; Part #: TP-20RD10-NO-POP
C10-C15 = CAP_NP_0: PART_N: 101587-1100R; Part #: 101587-1100R; REV: A
P9 = CONNECTOR_DB9_0: PART_N: 100558-0009R; Part #: 100558-0009R
R68 = RESISTOR_0: PART_N: 101370-0001R; Part #: 101370-0001R
R69 = RESISTOR_0: PART_N: R0402-NOPOP; Part #: R0402-NOPOP
R70 R71 = R: PART_N: 101370-2202R; Part #: 101370-2202R
U4 = TRS3386ECPWR: PART_N: 103164-0001R; Part #: 103164-0001R
C16 = CAPACITOR_POL_0: PART_N: 100396-0221R; Part #: 100396-0221R
C17 = CAPACITOR_POL_0: PART_N: 103119-0222R; Part #: 103119-0222R
C18 = CAP: PART_N: 100993-1100R; Part #: 100993-1100R
C20 = CAP: PART_N: 101497-0101R; Part #: 101497-0101R
C21 = CAP: PART_N: 101587-1101R; Part #: 101587-1101R
C22 = CAP: PART_N: 100395-0101R; Part #: 100395-0101R
C23 = CAP: PART_N: 101779-0102R; Part #: 101779-0102R
C24 = CAP: PART_N: 101007-0100R; Part #: 101007-0100R
L1 = INDUCTOR_0: PART_N: 101810-0101R; Part #: 101810-0101R
MTG4 = MOUNTING_SCREW_0: PN: MH095P_200; PN MFG: PCB; Part Vendor: WSTS
MTG5-MTG10 = MOUNTING_SCREW_2: PN: MH095P_200; PN MFG: PCB; Part Vendor: WSTS
R76 R77 R79 = R: PART_N: 100687-0001R; Part #: 100687-0001R
R80 = R: PART_N: 102145-2944R; Part #: 102145-2944R
R81 = R: PART_N: 102145-2004R; Part #: 102145-2004R
R82 = R: PART_N: 102145-1023R; Part #: 102145-1023R
U5 = TPS61093: PART_N: 103582-0001R; Part #: 103582-0001R

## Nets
DGND: C1.2 C6.2 C7.2 C10.1 C13.1 C14.1 C15.1 C16.2 C17.2 C18.2 C20.2 C22.2 C23.2 C24.2 C100.2 C102.2 C108.2 C210.2 C264.2 C265.2 C266.2 MTG4.1 MTG4.2 P1.1 P1.2 P2.1 P2.2 P2.43 P2.44 P2.45 P2.46 P3.5 P3.6 P3.18 P3.20 P3.22 P5.1(11) P5.19(20) P6.2(1) P9.5 P9.10 P9.11 Q4.S(SOURCE) Q5.S(SOURCE) R33.2 R35.2 R69.1 R81.2 R82.2 R83.1 R84.2 R170.1(P1) R212.2 R216.2 R223.2 R257.1(P1) R263.1 R264.1 SW1.1(A1) SW1.2(A2) TP1.1(PIN) U1.4(VSS) U4.9(DIN3) U4.18(GND) U5.1(GND) U5.11(PWR_PAD) U23.1(OE) U23.7(GND) U24.4(OE2) U24.10(OE3) U39.2(GND) U39.3(In0) U40.2(GND) U40.3(In0) U41.2(GND) U41.3(In0)
GND_AC_PWR: C5.1 D1.2(ANODE) P3.1 T1.4 TP2.1(PIN)
VDD_3V3EXP: C1.1 C6.1 C7.1 C10.2 C15.2 C100.1 C102.1 C108.1 C210.1 C264.1 C265.1 C266.1 ISO1.4(COLLECTOR) ISO2.4(COLLECTOR) ISO3.4(COLLECTOR) P2.3 P2.4 P6.9(15) R3.2 R4.2 R5.2 R6.2 R7.2 R8.1 R19.1 R37.1 R48.1 R49.1 R68.2 R70.1 R71.1 R72.1 R73.1 R74.1 R75.1 R167.1 R168.2 R169.2 U1.8(VCC) U4.12(VL) U4.19(VCC) U23.14(PWR) U39.5(VCC) U39.6(In2) U40.5(VCC) U40.6(In2) U41.5(VCC) U41.6(In2)
VDD_5V: C16.1 C17.1 C20.1 L1.1 P2.5 P2.6 R78.1 R256.2(P2) R258.2(P2) U5.2(VIN)
CC1_P0.0: P5.11(16) TP6.1(PIN)
CC1_P0.1: P5.5(13) R34.2
CC1_P0.2: P5.7(14) R36.2
CC1_P0.3: P5.9(15) R38.2
CC1_P0.4: P5.3(12) R32.2
CC1_P0.5: P6.18(9) R45.1
CC1_P0.6: P5.15(18) TP8.1(PIN)
CC1_P0.7: P5.17(19) TP9.1(PIN)
CC1_P1.0: P5.6(3) R30.2 TP5.1(PIN)
CC1_P1.1: P5.13(17) TP7.1(PIN)
CC1_P1.3: P5.4(2) TP4.1(PIN)
CC1_P1.4: P5.14(7) R41.1
CC1_P1.5: P5.16(8) R42.1
CC1_P1.6: P5.18(9) R44.1
CC1_P1.7: P5.20(10) R46.1
CC1_P2.0: P6.19(20) R47.2
CC1_P2.1: P5.10(5) R39.1
CC1_P2.2: P5.12(6) R40.1
EVM_15V: C21.1 C22.1 C23.1 R18.1 R76.2 R79.2 R80.1
GPIO0_26: P1.14 R34.1
GPIO0_27: P1.17 U24.9(I3)
GPIO1_12: P1.12 R32.1
GPIO1_13: P1.11 R47.1
GPIO1_14: P1.16 U23.2(I)
GPIO1_15: P1.15 U24.5(I2)
GPIO1_16: P2.15 R39.2
GPIO1_17: P2.16 R43.1
GPIO1_28: P2.12 R45.2
GPIO1_29: P1.26 R16.1
GPIO2_1: P1.18 R10.2
I2C2_SCL: P2.19 R3.1 U1.6(SCL) U4.8(DIN2)
I2C2_SDA: P2.20 R4.1 U1.5(SDA) U4.10(ROUT2)
L138_LED1: DS1.1(CATHODE) U23.3(O)
L138_LED2: DS2.1(CATHODE) U24.6(O2)
L138_LED3: DS3.1(CATHODE) U24.8(O3)
LINE_AC_A: JP3.2 L16.2 L17.2 R269.1
LINE_AC_B: JP4.2 L14.2 L15.2 R265.1
LINE_AC_C: JP5.2 L12.2 L13.2 R268.1
LINE_AC_N: C101.1 C103.1 C109.1 D2.1(CATHODE) D7.1(CATHODE) D9.1(CATHODE) JP2.2 Q1.3(COLLECTOR) Q2.3(COLLECTOR) Q3.3(COLLECTOR) T1.7
LINE_COMB: C2.1 C3.1 C4.1 T1.8
PL_TXRX: D1.1(CATHODE) JP1.2 P3.2 R20.1
PLC_3V3: P3.8 R19.2 R261.2 R262.2
PLC_15V: P3.7 R18.2
PLC_EN: P3.9 R16.2 R261.1 R263.2
PLC_LED1: Q4.G(GATE) R257.2(P2) R259.2
PLC_LED2: Q5.G(GATE) R170.2(P2) R260.1
PLC_PWM_GPIO04: JP24.1 P3.30
PLC_RESET: P3.29 R10.1 R262.1 R264.2
PLC_RX_A: P3.11 R14.2
PLC_RX_B: P3.33 R9.1
PLC_TX_A: P3.12 R15.1
PLC_TX_B: P3.34 R11.1
PLC_USBDP: JP23.2 P3.19
PLC_ZC: P3.10 R17.1
RESET_CC1: P6.15(18) R43.2
RSA_CTS: P9.8 U4.13(RIN2)
RSA_RTS: P9.7 U4.16(DOUT2)
RSA_RXD: P9.2 U4.14(RIN1)
RSA_TXD: P9.3 U4.17(DOUT1)
SPI1_CS0: JP6.2 P2.28
SPI1_CS0_A: JP6.1 R41.2 R48.2
SPI1_CS0_B: JP6.3 R49.2
SPI1_D0: P2.29 R44.2
SPI1_D1: P2.30 R46.2
SPI1_SCLK: P2.31 R42.2
SYS_5V: P2.7 P2.8
TIMER5: P1.9 R40.2
TIMER6: P1.10
UART1_RXD: JP8.2 P2.26
UART1_RXD_PLC: JP8.3 R15.2 R75.2
UART1_RXD_RS232: JP8.1 R71.2 R74.2 U4.11(ROUT1)
UART1_TXD: JP7.2 P2.24
UART1_TXD_PLC: JP7.3 R14.1 R73.2
UART1_TXD_RS232: JP7.1 R70.2 R72.2 U4.7(DIN1)
UART2_RXD: P2.22 R11.2
UART2_TXD: P2.21 R9.2
UART4_RXD: P2.11 R31.1 R38.1
UART4_TXD: P2.13 R30.1 R36.1
WP: R8.2 U1.7(WP)
ZERO_PLC_A: R17.2 U39.4(Y)
ZERO_PLC_B: JP24.2 U40.4(Y)
ZERO_PLC_C: JP23.1 U41.4(Y)
N16778414: R7.1 SW1.4(B1) U1.1(A0)
N16778419: R6.1 SW1.3(B2) U1.2(A1)
N16778424: R5.1 U1.3(A2)
N16826038: P3.14 R84.1
N16826043: P3.13 R83.2
N16828319: L1.2 U5.9(SW)
N16828387: C19.2 U5.3(CP2)
N16828418: C19.1 U5.4(CP1)
N16828454: R78.2 U5.5(EN)
N16828525: C24.1 R81.1 U5.6(SS)
N16830241: C21.2 R80.2 R82.1 U5.7(FB)
N16830614: C18.1 R76.1 R77.2
N16855212: JP5.1 P4.5
N16855216: JP2.1 P4.1
N16855243: T1.2 T1.3
N16855245: JP3.1 P4.3
N16855250: JP1.1 T1.1
N16855264: C5.2 R20.2
N16855317: JP4.1 P4.4
N16855337: JP22.1 L12.1
N16855339: JP22.3 L13.1
N16855363: JP21.1 L14.1
N16855365: JP21.3 L15.1
N16855389: JP20.1 L16.1
N16855391: JP20.3 L17.1
N16855430: C4.2 JP22.2
N16855436: C3.2 JP21.2
N16855446: C2.2 JP20.2
N16858528: D12.1(Cathode) Q4.D(DRAIN)
N16858532: D12.2(Anode) R258.1(P1)
N16858616: D13.1(Cathode) Q5.D(DRAIN)
N16858620: D13.2(Anode) R256.1(P1)
N16858701: P3.24 R259.1
N16858745: P3.23 R260.2
N16860071: ISO1.3(EMITTER) R210.1 R212.1
N16860073: C101.2 D2.2(ANODE) D14.ANODE(A) ISO1.2(CATHODE) R209.1
N16860077: ISO1.1(ANODE) R211.2
N16860100: Q1.2(EMITTER) R211.1
N16860121: R2.1 R265.2
N16860123: R1.1 R2.2
N16860125: D14.CATHODE(K) Q1.1(BASE) R1.2 R209.2
N16860151: ISO2.3(EMITTER) R214.1 R216.1
N16860153: C103.2 D6.ANODE(A) D7.2(ANODE) ISO2.2(CATHODE) R213.1
N16860157: ISO2.1(ANODE) R215.2
N16860180: Q2.2(EMITTER) R215.1
N16860201: R268.2 R270.1
N16860203: R266.1 R270.2
N16860205: D6.CATHODE(K) Q2.1(BASE) R213.2 R266.2
N16860293: R218.2 U39.1(In1)
N16860345: R210.2 U40.1(In1)
N16860397: R214.2 U41.1(In1)
N16860403: ISO3.3(EMITTER) R218.1 R223.1
N16860781: C109.2 D8.ANODE(A) D9.2(ANODE) ISO3.2(CATHODE) R217.1
N16860785: ISO3.1(ANODE) R222.2
N16860806: Q3.2(EMITTER) R222.1
N16860827: R12.1 R269.2
N16860829: R12.2 R267.1
N16860831: D8.CATHODE(K) Q3.1(BASE) R217.2 R267.2
N16894704: DS2.2(ANODE) R168.1
N16894705: DS1.2(ANODE) R167.2
N16894708: DS3.2(ANODE) R169.1
N18406157: P5.8(4) R31.2
N18407827: P5.2(1) TP3.1(PIN)
N18411100: P6.4(2) R33.1
N18411132: P6.6(3) R35.1
N18411342: P6.7(14) R37.2
N19029479: R79.1 U5.8(OUT)
N19029551: R77.1 U5.10(VO)
N22163966: C11.2 U4.4(C2+)
N22163967: C11.1 U4.5(C2-)
N22163968: C12.1 U4.3(C1-)
N22163969: C12.2 U4.1(C1+)
N22163982: C13.2 U4.2(V+)
N22163983: C14.2 U4.6(V-)
N22367415: R68.1 R69.2 U4.20(~{PWRDOWN})

Not connected (* = marked no-connect by the designer): MTG5 1*; MTG6 1*; MTG7 1*; MTG8 1*; MTG9 1*; MTG10 1*; P1 3 4 5 6 7* 8* 13* 19* 20 21* 22* 23* 24* 25* 27* 28* 29* 30* 31* 32* 33* 34* 35* 36* 37* 38* 39* 40* 41* 42* 43* 44* 45* 46*; P2 9* 10* 14* 17* 18* 23* 25* 27* 32* 33* 34* 35* 36* 37* 38* 39* 40* 41* 42*; P3 3* 4* 15* 16* 17* 21* 25* 26* 27* 28* 31* 32*; P4 2; P6 1(11)* 3(12)* 5(13)* 8(4)* 10(5)* 11(16)* 12(6)* 13(17)* 14(7)* 16(8)* 17(19)* 20(10)*; P9 1* 4* 6* 9*; T1 5* 6* 9*; U4 15(DOUT3)*

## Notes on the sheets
sheet 2
- Rev
- Description
- Date
- By
- Page No.
- Schematic Page
- 1.0
- Initial release.
- 06/11/12
- GM
- 1
- Title Page
- 1.1
- Corrected few bugs on PLC SOM
  interface, added LEDs, changed 5V
  DC  source to BBone.
- 06/18/12
- GM
- 2
- BeagleBone Interface
- 3
- PLC SOM Connector
- 1.2
- Added missing pin information to
  optocoupler in zero crossing circuit.
- 06/19/12
- GM
- 4
- PLC Interface
- 5
- Zero Crossing Detector
- 1.3
- Corrected few bugs: PLC_15V
  connected incorrectly, made ADC
  power and ground NC, wrong ground
  used in LED buffer, corrected name of
  AC ground.
- 07/09/12
- 6
- CC Interface 1
- 7
- RS232 Connector
- GM
- 8
- Power
- 1.4
- Fixed floating 3V3 source for
  zero-crossing circuit.
- 08/01/12
- GM
- 1.5
- ---
- 18/04/14
- GM
- 1.6
- a.
- Compatible to BAGLE BONE BLACK.
- b.
- PLC capacitive coupling circuit made same as
- data concentrator.
- GM
- 18/04/14
- c.
- Zero crossing and som connector made
- same as  concentrator
sheet 3
- NOTE: DIMENSIONS AND LOCATIONS OF THESE CONNECTORS  MUST MEET SPECIFICATION FOR INTERFACE MODULES
  REFERENCE CC2530EMK USER GUIDE (SWRU208) OR SMART GRID EVM DESIGN FILES
- Connector P/N: TFM-110-02-SM-D-A-K-TR (Samtec)
- 1
- 1
- P1
- ON CC MODULES
- P2
- P5
- ON SMART GRID BOARD
- P6
sheet 4
- Note Board Markings required
- HAZZARD MARKING
- CURRENT AND VOLTAGE
  MARKINGS
- SD PART# 103531-0001R
sheet 5
- NOTE: KEEP OUT REGION EXISTS AROUND THIS CONNECTOR IN ORDER TO ACCOMODATE PLC SOM
  REFERENCE SMART GRID EVM DESIGN FILES
- L1
- L2
sheet 6
- UART1_RTSN
- UART1_CTSN
sheet 7
- BeagleBone must supply 5VDC power from external power supply.
  Recommended power supply: CUI Inc., 5V/2A, EMMA050200-P5.
sheet 8
- TSHC-123-D-03-145-GT-LF
- TSHC-123-D-03-145-GT-LF
- EXPANSION HEADER
- EXPANSION HEADER
- UART4_RXD, UART4_TXD => RF
- UART5_RXD, UART5_TXD => RF
- UART1_RTSN (I2C_SCL), UART1_CTSN (I2C_SDA), UART1_RXD, UART1_TXD => PLC (PORTA)
- UART2_RXD, UART2_TXD => PLC (PORTB)
- SPI1 (CS0, SCLK, D0, D1) => CC1 & CC2
- TIMER5  => CC1
- TIMER6  => CC2
- Expansion Board EEPROM
- 256KX8
